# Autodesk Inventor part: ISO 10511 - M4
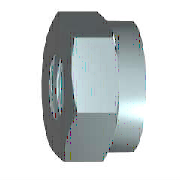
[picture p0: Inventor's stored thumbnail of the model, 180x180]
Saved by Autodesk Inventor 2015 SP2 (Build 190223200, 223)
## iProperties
IsCustomPart: 0
Created: 2012-02
Part Number: ISO 10511 - M4
Material: Stahl, weich
Description: Sechskantmutter
Document SubType Name: Modeling
Standard: ISO 10511
Designer: rYan
Standard Revision: 1998
Standards Organization: DIN
Language: de-DE
Size Designation: M4
Categories: <MemberInstance><Categories><Category DisplayName="Verbindungselemente" InternalName="e4da775c-781d-43d5-af7c-5136215cf5a6" Mnemonic="FSTN"><Category DisplayNam
Density: 7.85 g/cm^3
Mass: 0.918896 g
Surface Area: 2.04052 cm^2
Volume: 0.117057 cm^3
Appearance: Halbpoliert
Author: rYan
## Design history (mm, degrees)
sketch "Skizze1"
  geometry: L1 (2.021, -3.5)-(-2.021, -3.5); L2 (-2.021, -3.5)-(-4.041, 0); L3 (-4.041, 0)-(-2.021, 3.5); L4 (-2.021, 3.5)-(2.021, 3.5); L5 (2.021, 3.5)-(4.041, 0); L6 (4.041, 0)-(2.021, -3.5); 2 further points
  constraints: 12 end point, 1 coincident, 1 horizontal, 11 other
  dimensions: "d0" = 8.0829 distance of L5.end L2.end (= 1.1547 x SW)
extrude "Körper" new body sketch "Skizze1" distance "d1" = 1.95 (= KOH1); taper "d2" = 0 deg
sketch "Skizze2"
  geometry: C1 r 2.95 at (0, 0); 1 further point
  constraints: 1 centre point, 1 coincident
  dimensions: "d7" = 5.9 diameter of C1 (= SD2)
extrude "Ring" join sketch "Skizze2" distance "d8" = 3.05 (= KOH - KOH1); taper "d9" = 0 deg
sketch "Skizze3"
  geometry: L1 (0, 2.021)-(0, 4.041) reference; L2 (0, 4.041)-(1.95, 4.041) reference; L3 (1.95, 2.021)-(1.95, 4.041) reference; L4 (-0.39, 0)-(2.34, 0) reference; L5 (0, 2.95)-(0.63, 4.041); L6 (1.32, 4.041)-(1.95, 2.95)
  constraints: 4 end point, 4 point on line
  dimensions: "d3" = 30 deg angle of L5 L1 (= ANG1); "d4" = 30 deg angle of L3 L6 (= ANG2); "d5" = 5.9 diameter of L5.start L4 (= SW0); "d6" = 5.9 diameter of L6.end L4 (= SW01)
revolve "Fase1" sketch "Skizze3" stored, may be unused: angle "d26" = 90 deg
sketch "Skizze4"
  geometry: L1 (0, -5.658)-(0, 5.658) reference; L2 (-4.9, 0)-(4.9, 0) reference; 1 further point
  constraints: 2 midpoint
hole "Gewinde" sketch "Skizze4" at (0, 0) diameter "d30" = 3.242; stored, may be unused: countersink angle "d34" = 82 deg, drill point angle "d36" = 118 deg; dims "d31" = 6, "d32" = 4, "d33" = 2, "d35" = 8
workaxis "Work Axis1"
workplane "Work Plane1"
body "Solid1"
chamfer "Fase2" distance "d10" = 0.37889 (= -0.5 x GD1 + 0.5 x NND); stored, may be unused: angle "d11" = 30 deg, second distance "d46" = 0.37889 (= -0.5 x GD1 + 0.5 x NND)
chamfer "Fase3" distance "d12" = 0.37889 (= -0.5 x GD1 + 0.5 x NND); stored, may be unused: angle "d13" = 30 deg, second distance "d47" = 0.37889 (= -0.5 x GD1 + 0.5 x NND)
other parameters: "ANG1" = 30 deg [user parameter; used in 1 equation term], "ANG2" = 30 deg [user parameter; used in 1 equation term], "NND" = 4 [user parameter; used in 4 equation terms], "KOH1" = 1.95 [user parameter; used in 2 equation terms], "KOH" = 5 [user parameter; used in 1 equation term], "SW" = 7 [user parameter; used in 2 equation terms], "SW0" = 5.9 [user parameter; used in 3 equation terms], "SW01" = 5.9 (= SW0) [user parameter; used in 1 equation term], "SD2" = 5.9 (= SW0) [user parameter; used in 1 equation term], "GD1" = 3.24223 (computed from THREADDIA, PTC, TOA) [user parameter; used in 4 equation terms], "d14" = 0, "d15" = 0, "d45" = 0, "d48" = 0, "GUL" = 0.37889 (= 0.541266 x PTC) [user parameter], "TPU" = 14.28571 (computed from PTC) [user parameter], "THREADDIA" = 4 [user parameter; used in 1 equation term], "TOA" = 30 deg [user parameter; used in 1 equation term], "PTC" = 0.7 [user parameter; used in 4 equation terms], "E0" = 8.085 (= 1.155 x SW) [user parameter], "GAL" = 0.37889 (= 0.541266 x PTC) [user parameter]
